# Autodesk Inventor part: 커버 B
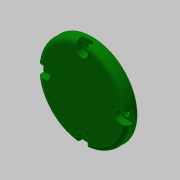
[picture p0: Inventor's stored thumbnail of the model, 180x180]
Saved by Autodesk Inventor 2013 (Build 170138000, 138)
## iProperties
Created: 2019-05
Part Number: 커버 B
Material: 알루미늄 6061
Document SubType Name: Modeling
Designer: mduedu
Density: 1 g/cm^3
Author: mduedu
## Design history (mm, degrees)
sketch "스케치1"
  geometry: C1 r 31 at (0, 0); 1 further point
  constraints: 1 centre point, 1 coincident
  dimensions: "d0" = 62 diameter of C1
extrude "돌출1" new body sketch "스케치1" distance "d1" = 7; taper "d2" = 0 deg
sketch "스케치3"
  geometry: C1 r 20 at (0, 0); 1 further point
  constraints: 1 centre point, 1 coincident
  dimensions: "d7" = 40 diameter of C1
extrude "돌출3" join sketch "스케치3" distance "d8" = 4; taper "d9" = 0 deg
sketch "스케치4"
  geometry: C1 r 17 at (0, 0); 1 further point
  constraints: 1 centre point, 1 coincident
  dimensions: "d10" = 34 diameter of C1
extrude "돌출4" cut sketch "스케치4" distance "d11" = 3; taper "d12" = 0 deg
fillet "모깎기3" dims "d20" = 3
fillet "모깎기4" dims "d21" = 3
chamfer "모따기1" distance "d22" = 1; stored, may be unused: second distance "d23" = 2, angle "d24" = 45 deg
sketch "스케치7" dims "d25" = 52
  geometry: L1 (-4, 26)-(-4, 30.741); L2 (4, 26)-(4, 30.741); A1 r 4 centre (0, 26) between (-4, 26) and (4, 26); A2 r 31 centre (0, 0) between (4, 30.741) and (-4, 30.741); 3 further points
  constraints: 4 end point, 4 point on circle, 2 centre point, 2 coincident, 2 tangent, 2 vertical alignment, 1 parallel, 1 vertical, 4 other
  dimensions: "d26" = 8 distance between parallel lines of L2 L1
extrude "돌출7" cut sketch "스케치7" distance "d27" = 4.4; taper "d28" = 0 deg
sketch "스케치8" dims "d36" = 52
  geometry: 6 further points
  constraints: 2 vertical alignment, 1 coincident, 7 other
  dimensions: "d39" = 360 deg dimension on point (0, 0) point (0, 26) (derived)
sketch "스케치9"
  geometry: 4 further points
  constraints: 4 other
hole "구멍1" sketch "스케치9" at (0, 52), (-26, 26), (26, 26), (0, 0) diameter "d41" = 4.5; stored, may be unused: countersink angle "d45" = 90 deg, drill point angle "d47" = 0 deg; dims "d42" = 6, "d43" = 4, "d44" = 2, "d46" = 8
node "솔리드1"
pattern_circular "원형 패턴1" dims angle "d30" = 360 deg
